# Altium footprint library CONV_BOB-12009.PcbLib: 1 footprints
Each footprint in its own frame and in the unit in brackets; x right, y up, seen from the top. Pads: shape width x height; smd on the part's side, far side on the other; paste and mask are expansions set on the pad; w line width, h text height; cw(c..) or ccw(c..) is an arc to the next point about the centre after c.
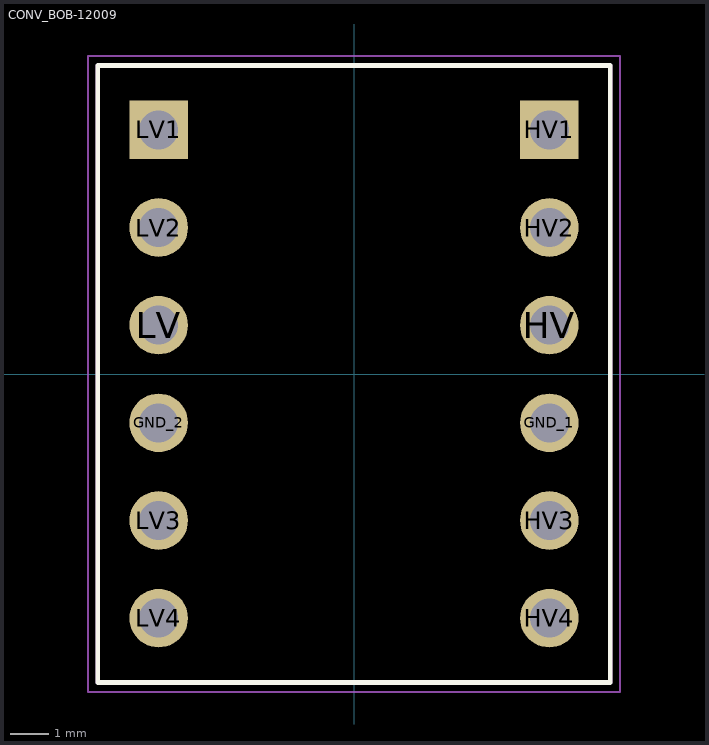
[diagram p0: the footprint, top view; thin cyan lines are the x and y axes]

## CONV_BOB-12009 [mil]
pads (12):
  round 60 hole 40: GND_1(200,-50) GND_2(-200,-50) HV(200,50) HV2(200,150) HV3(200,-150) HV4(200,-250) LV(-200,50) LV2(-200,150) LV3(-200,-150) LV4(-200,-250)
  rect 60x60 / inner round 60 / far side rect 60x60 hole 40: HV1(200,250) LV1(-200,250)
Top Overlay:
  lines w5: -262.4,-315.94 -262.4,315.94 262.4,315.94 262.4,-315.94 -262.4,-315.94
Assembly Top:
  lines w5: -262.4,-315.94 -262.4,315.94 262.4,315.94 262.4,-315.94 -262.4,-315.94
Courtyard Top:
  lines w1.97: -272.24,-325.79 272.24,-325.79 272.24,325.79 -272.24,325.79 -272.24,-325.79
3D body "step_temp.STEP": height 110.24, standoff 0, extent -262.4,-315.94 262.4,315.94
